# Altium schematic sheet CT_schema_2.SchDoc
size 293 x 134 mm
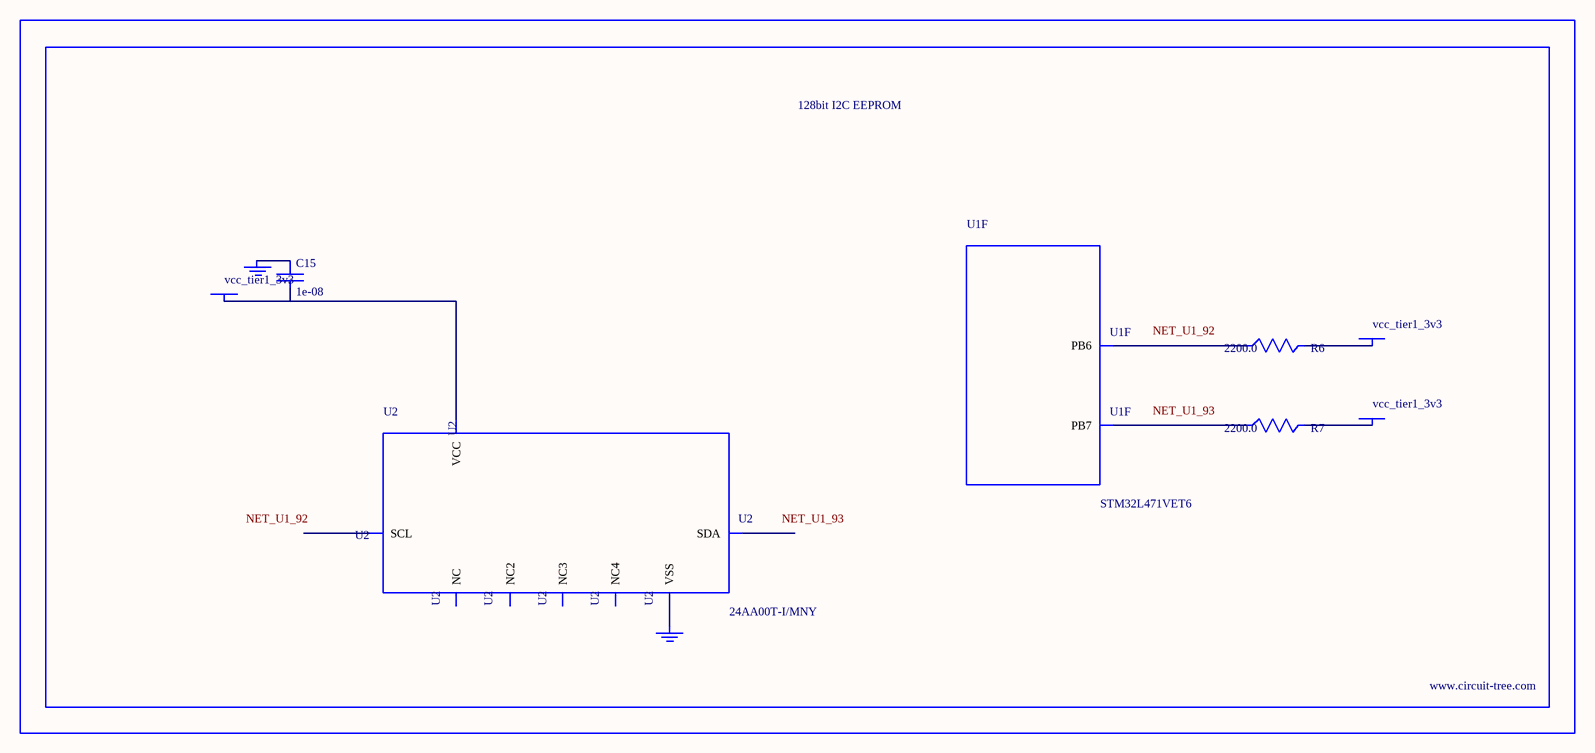
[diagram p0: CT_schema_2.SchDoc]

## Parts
BORDER1  (no value)
C15  1e-08  [C0402]
GND_INSTANCE_1_0  (no value)
GND_INSTANCE_1_1  (no value)
POWER_INSTANCE_1_0  vcc_tier1_3v3
POWER_INSTANCE_1_1  vcc_tier1_3v3
POWER_INSTANCE_1_2  vcc_tier1_3v3
R6  2200.0  [R0603]
R7  2200.0  [R0603]
U1  STM32L471VET6  [LQFP100]  (part F of 11)
U2  24AA00T-I/MNY  [TDFN-8/6MM]

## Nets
NetC15_1: C15.1 GND_INSTANCE_1_0.0(GND)
NetC15_2: C15.2 POWER_INSTANCE_1_0.0(PWR) U2.8(VCC)
NetGND_INSTANCE_1_1_0: GND_INSTANCE_1_1.0(GND) U2.4(VSS)
NetPOWER_INSTANCE_1_1_0: POWER_INSTANCE_1_1.0(PWR) R6.2
NetPOWER_INSTANCE_1_2_0: POWER_INSTANCE_1_2.0(PWR) R7.2
NetR6_1: R6.1 U1.92(PB6)
NetR7_1: R7.1 U1.93(PB7)

Not connected (* = marked no-connect by the designer): U2 1(NC) 2(NC2) 3(NC3) 5(SDA) 6(SCL) 7(NC4)

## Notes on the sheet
- Labels drawn without touching a wire or pin: NET_U1_92, NET_U1_93

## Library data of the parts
BORDER1 = BORDER_PAGE1
C15 = C0402C103K3RAC
GND_INSTANCE_1_0 GND_INSTANCE_1_1 = GND
POWER_INSTANCE_1_0-POWER_INSTANCE_1_2 = PWR
R6 R7 = RC0603JR-072K2L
